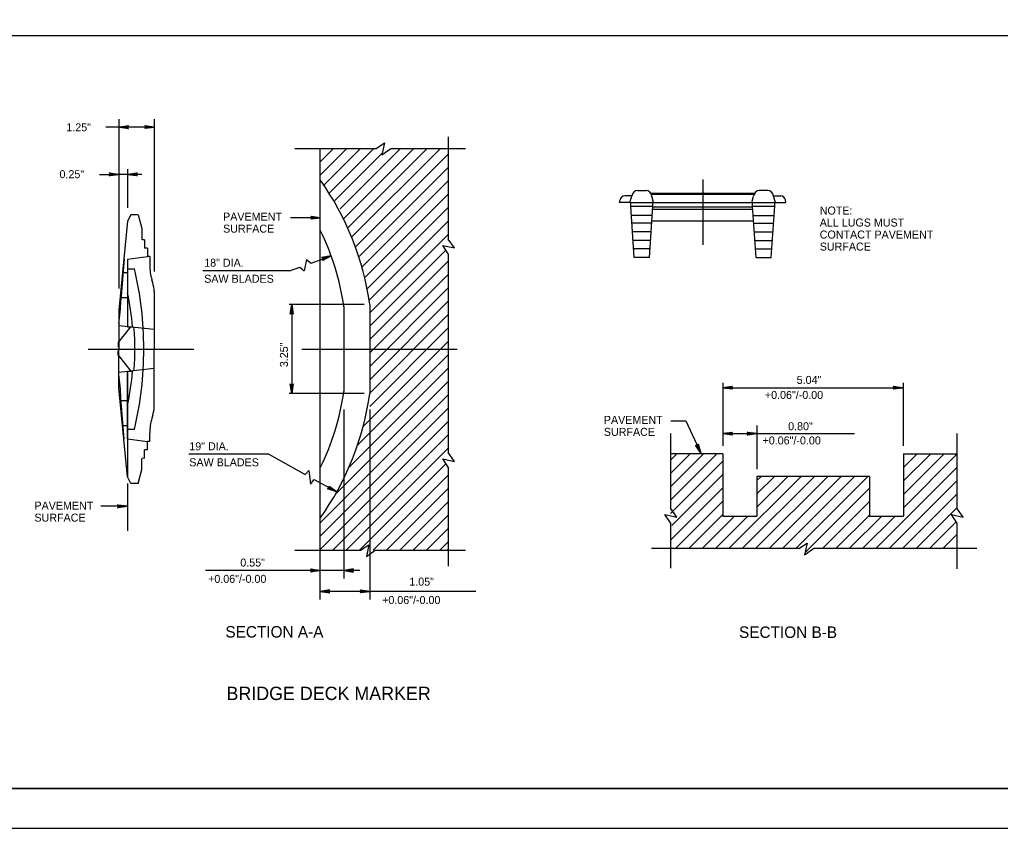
# Model space of a CAD drawing. Extents: x 639362 to 641108, y 298458 to 299646.
# Drawn here: x 640431.7 to 640799.3, y 298457.6 to 298760.6 of the extents above; entities that cross this region are included whole.
import ezdxf

# ---------------------------------------------------------------- set-up
doc = ezdxf.new("R2010")
doc.units = 0
for name, color, linetype in [('1', 7, 'Continuous'), ('2', 7, 'Continuous'), ('PLT-BNDY', 7, 'Continuous')]:
    doc.layers.add(name, color=color, linetype=linetype)

msp = doc.modelspace()

# ---------------------------------------------------------------- linework, layer by layer
at = {"layer": '1'}
for p, q in [((640243.31, 298754.63), (640829.31, 298754.63)), ((641029.31, 298472.63), (640243.31, 298472.63)), ((640243.31, 298472.63), (640829.31, 298472.63))]:
    msp.add_line(p, q, dxfattribs=at)
at = {"layer": '2'}
for p, q in [((640468.92, 298723.36), (640468.92, 298659.92)), ((640482.21, 298723.36), (640482.21, 298666.21)), ((640482.21, 298720.36), (640463.98, 298720.36)), ((640565.36, 298712.39), (640568.44, 298714.44)), ((640568.44, 298714.44), (640567.53, 298710.04)), ((640592.33, 298716.72), (640592.33, 298678.38)), ((640534.93, 298712.39), (640565.36, 298712.39)), ((640544.39, 298712.38), (640544.41, 298712.39)), ((640544.39, 298707.37), (640549.41, 298712.39)), ((640544.39, 298702.36), (640554.42, 298712.39)), ((640544.39, 298543.43), (640544.39, 298712.39)), ((640545.44, 298698.39), (640559.43, 298712.39)), ((640547.68, 298695.63), (640564.44, 298712.39)), ((640549.92, 298692.86), (640567.64, 298710.58)), ((640551.84, 298689.77), (640574.46, 298712.39)), ((640553.08, 298686), (640579.47, 298712.39)), ((640554.68, 298682.59), (640584.48, 298712.39)), ((640556.17, 298679.08), (640589.48, 298712.39)), ((640567.53, 298710.04), (640570.82, 298712.39)), ((640570.82, 298712.39), (640598.86, 298712.39)), ((640557.56, 298675.46), (640592.33, 298710.23)), ((640472.14, 298704.67), (640472.14, 298690.08)), ((640558.84, 298671.73), (640592.33, 298705.22)), ((640461.63, 298702.66), (640468.92, 298702.66)), ((640477.55, 298702.66), (640468.92, 298702.66)), ((640560, 298667.88), (640592.33, 298700.21)), ((640687.74, 298700.77), (640687.74, 298676.31)), ((640663.27, 298696.59), (640666.56, 298696.59)), ((640712.21, 298696.59), (640708.92, 298696.59)), ((640561.03, 298663.91), (640592.33, 298695.2)), ((640656.61, 298692.1), (640656.76, 298693.07)), ((640660.72, 298692.1), (640656.61, 298692.1)), ((640661.18, 298694.57), (640658.51, 298694.57)), ((640660.47, 298692.1), (640661.17, 298694.53)), ((640660.47, 298692.1), (640669.35, 298692.1)), ((640660.76, 298690.78), (640660.76, 298692.1)), ((640668.24, 298695.6), (640707.24, 298695.6)), ((640668.46, 298695.2), (640707.06, 298695.2)), ((640669.35, 298692.1), (640668.66, 298694.53)), ((640669.06, 298690.78), (640669.06, 298692.1)), ((640669.1, 298692.1), (640706.37, 298692.1)), ((640706.13, 298692.1), (640706.82, 298694.53)), ((640706.13, 298692.1), (640715, 298692.1)), ((640706.41, 298690.78), (640706.41, 298692.1)), ((640714.3, 298694.57), (640716.97, 298694.57)), ((640715, 298692.1), (640714.31, 298694.53)), ((640714.72, 298690.78), (640714.72, 298692.1)), ((640714.76, 298692.1), (640718.87, 298692.1)), ((640718.87, 298692.1), (640718.72, 298693.07)), ((640561.93, 298659.79), (640592.33, 298690.19)), ((640662.09, 298671.5), (640660.76, 298690.78)), ((640660.76, 298690.78), (640669.06, 298690.78)), ((640667.74, 298671.5), (640669.06, 298690.78)), ((640668.98, 298689.63), (640706.49, 298689.63)), ((640669.05, 298690.55), (640706.43, 298690.55)), ((640707.74, 298671.5), (640706.41, 298690.78)), ((640706.41, 298690.78), (640714.72, 298690.78)), ((640713.38, 298671.5), (640714.72, 298690.78)), ((640472.14, 298685.17), (640468.92, 298651.74)), ((640473.47, 298687.55), (640472.14, 298685.17)), ((640476.19, 298687.55), (640473.47, 298687.55)), ((640476.19, 298687.55), (640477.59, 298682.33)), ((640544.39, 298686.43), (640533.26, 298686.43)), ((640562.68, 298655.53), (640592.33, 298685.18)), ((640668.82, 298687.21), (640661.01, 298687.21)), ((640668.69, 298685.3), (640706.79, 298685.3)), ((640706.66, 298687.21), (640714.47, 298687.21)), ((640477.59, 298682.33), (640477.59, 298678.19)), ((640668.62, 298684.35), (640661.2, 298684.35)), ((640668.4, 298681.14), (640661.43, 298681.14)), ((640706.85, 298684.35), (640714.27, 298684.35)), ((640707.08, 298681.14), (640714.05, 298681.14)), ((640478.57, 298678.17), (640477.7, 298678.19)), ((640478.57, 298678.17), (640478.57, 298675.06)), ((640562.92, 298650.77), (640592.33, 298680.18)), ((640594.68, 298675.09), (640592.33, 298678.38)), ((640668.18, 298677.93), (640661.65, 298677.93)), ((640707.3, 298677.93), (640713.83, 298677.93)), ((640479.64, 298675.04), (640478.57, 298675.06)), ((640479.64, 298675.04), (640479.64, 298671.93)), ((640562.92, 298645.76), (640591.43, 298674.27)), ((640592.33, 298672.91), (640590.28, 298675.99)), ((640590.28, 298675.99), (640594.68, 298675.09)), ((640667.96, 298674.71), (640661.87, 298674.71)), ((640707.52, 298674.71), (640713.6, 298674.71)), ((640470.85, 298670.98), (640469.68, 298655.59)), ((640472.14, 298670.91), (640479.64, 298671.93)), ((640472.14, 298670.91), (640472.14, 298645.64)), ((640480.51, 298671.91), (640479.64, 298671.93)), ((640480.51, 298671.91), (640480.51, 298668.68)), ((640539.27, 298670.8), (640538.32, 298666.53)), ((640539.27, 298670.8), (640540.95, 298669.38)), ((640540.95, 298669.38), (640548.48, 298672.12)), ((640562.92, 298640.75), (640592.33, 298670.16)), ((640592.33, 298672.91), (640592.33, 298598.42)), ((640667.74, 298671.5), (640662.09, 298671.5)), ((640707.74, 298671.5), (640713.38, 298671.5)), ((640472.14, 298667.32), (640474.77, 298667.32)), ((640532.89, 298666.46), (640500.42, 298666.46)), ((640532.89, 298666.46), (640536.74, 298667.86)), ((640536.74, 298667.86), (640538.32, 298666.53)), ((640470.46, 298665.86), (640472.14, 298665.86)), ((640481.61, 298662.05), (640481.29, 298663.16)), ((640562.92, 298635.74), (640592.33, 298665.15)), ((640562.92, 298630.73), (640592.33, 298660.14)), ((640469.68, 298656.51), (640472.14, 298656.51)), ((640482.14, 298658.81), (640482.14, 298637.23)), ((640468.92, 298651.74), (640468.92, 298637.23)), ((640560.92, 298653.87), (640532.71, 298653.87)), ((640533.71, 298653.87), (640533.71, 298620.58)), ((640553.25, 298653.19), (640553.25, 298621.27)), ((640562.92, 298625.73), (640592.33, 298655.13)), ((640562.92, 298653.87), (640562.92, 298620.58)), ((640562.92, 298620.72), (640592.33, 298650.12)), ((640468.65, 298639.55), (640473.41, 298645.55)), ((640482.14, 298644.53), (640468.92, 298645.97)), ((640472.14, 298645.53), (640473.69, 298645.53)), ((640562.92, 298615.71), (640592.33, 298645.11)), ((640457.4, 298637.23), (640496.99, 298637.23)), ((640468.65, 298639.55), (640468.65, 298637.97)), ((640468.92, 298622.71), (640468.92, 298637.23)), ((640482.14, 298615.64), (640482.14, 298637.23)), ((640537.51, 298637.23), (640595.72, 298637.23)), ((640560.45, 298608.23), (640592.33, 298640.1)), ((640468.65, 298634.9), (640468.65, 298636.49)), ((640468.65, 298634.9), (640473.41, 298628.91)), ((640558.29, 298601.06), (640592.33, 298635.1)), ((640482.14, 298629.92), (640468.92, 298628.48)), ((640555.13, 298592.89), (640592.33, 298630.09)), ((640472.14, 298628.93), (640473.69, 298628.93)), ((640472.14, 298628.81), (640472.14, 298589.29)), ((640472.14, 298603.55), (640472.14, 298628.81)), ((640472.14, 298589.29), (640468.92, 298622.71)), ((640550.12, 298582.87), (640592.33, 298625.08)), ((640695.32, 298624.5), (640695.32, 298601)), ((640695.32, 298622.72), (640762.65, 298622.72)), ((640762.82, 298624.5), (640762.82, 298601)), ((640470.85, 298603.47), (640469.68, 298618.86)), ((640560.92, 298620.58), (640532.71, 298620.58)), ((640544.39, 298572.13), (640592.33, 298620.07)), ((640469.68, 298617.94), (640472.14, 298617.94)), ((640544.39, 298567.13), (640592.33, 298615.06)), ((640481.61, 298612.41), (640481.29, 298611.29)), ((640553.25, 298614.58), (640553.25, 298551.25)), ((640562.92, 298614.58), (640562.92, 298543.43)), ((640470.46, 298608.59), (640472.14, 298608.59)), ((640544.39, 298562.12), (640592.33, 298610.05)), ((640675.82, 298610.34), (640681.38, 298610.34)), ((640681.38, 298610.34), (640687.01, 298598.21)), ((640708.07, 298608.54), (640708.07, 298592.22)), ((640472.14, 298607.14), (640474.77, 298607.14)), ((640480.51, 298602.55), (640480.51, 298605.78)), ((640549.15, 298561.86), (640592.33, 298605.04)), ((640675.65, 298605.61), (640675.65, 298577.57)), ((640695.32, 298605.54), (640744.68, 298605.54)), ((640783.03, 298605.61), (640783.03, 298577.57)), ((640472.14, 298603.55), (640479.64, 298602.53)), ((640480.51, 298602.55), (640479.64, 298602.53)), ((640479.64, 298599.42), (640479.64, 298602.53)), ((640479.64, 298599.42), (640478.57, 298599.4)), ((640478.57, 298596.29), (640478.57, 298599.4)), ((640525.09, 298597.85), (640495.09, 298597.85)), ((640525.09, 298597.85), (640538.78, 298590.23)), ((640554.15, 298561.86), (640592.33, 298600.04)), ((640594.68, 298595.13), (640592.33, 298598.42)), ((640695.32, 298598), (640675.65, 298598)), ((640675.65, 298595.64), (640678.02, 298598)), ((640675.65, 298590.63), (640683.03, 298598)), ((640675.65, 298585.62), (640688.04, 298598)), ((640675.65, 298580.61), (640693.04, 298598)), ((640695.32, 298598), (640695.32, 298574.53)), ((640762.96, 298598), (640762.96, 298574.63)), ((640762.96, 298598), (640783.03, 298598)), ((640762.96, 298582.78), (640778.19, 298598)), ((640762.96, 298587.78), (640773.18, 298598)), ((640762.96, 298592.79), (640768.17, 298598)), ((640762.96, 298577.77), (640783.03, 298597.84)), ((640477.59, 298592.12), (640477.59, 298596.27)), ((640478.57, 298596.29), (640477.7, 298596.27)), ((640559.16, 298561.86), (640591.5, 298594.2)), ((640592.33, 298592.95), (640590.28, 298596.03)), ((640590.28, 298596.03), (640594.68, 298595.13)), ((640592.33, 298592.95), (640592.33, 298555.85)), ((640675.65, 298575.6), (640695.32, 298595.27)), ((640752.65, 298562.45), (640783.03, 298592.83)), ((640473.47, 298586.9), (640472.14, 298589.29)), ((640476.19, 298586.9), (640477.59, 298592.12)), ((640538.78, 298590.23), (640540.06, 298591.76)), ((640540.06, 298591.76), (640540.71, 298586.58)), ((640564.17, 298561.86), (640592.33, 298590.02)), ((640676.16, 298571.1), (640695.32, 298590.27)), ((640697.56, 298562.45), (640724.61, 298589.5)), ((640702.57, 298562.45), (640729.62, 298589.5)), ((640707.58, 298562.45), (640734.63, 298589.5)), ((640708.07, 298589.5), (640708.07, 298574.63)), ((640750.21, 298589.5), (640708.07, 298589.5)), ((640708.07, 298587.99), (640709.59, 298589.5)), ((640708.07, 298582.98), (640714.6, 298589.5)), ((640708.07, 298577.97), (640719.6, 298589.5)), ((640712.59, 298562.45), (640739.64, 298589.5)), ((640717.59, 298562.45), (640744.65, 298589.5)), ((640722.6, 298562.45), (640749.66, 298589.5)), ((640750.21, 298589.5), (640750.21, 298574.53)), ((640472.14, 298586.8), (640472.14, 298569.08)), ((640476.19, 298586.9), (640473.47, 298586.9)), ((640540.71, 298586.58), (640542.17, 298588.34)), ((640542.17, 298588.34), (640550.57, 298583.67)), ((640757.66, 298562.45), (640783.03, 298587.82)), ((640569.18, 298561.86), (640592.33, 298585.01)), ((640675.65, 298565.59), (640695.32, 298585.26)), ((640726.11, 298560.95), (640750.21, 298585.05)), ((640762.67, 298562.45), (640783.03, 298582.81)), ((640472.04, 298578.32), (640462.16, 298578.32)), ((640574.19, 298561.86), (640592.33, 298580)), ((640677.53, 298562.45), (640695.32, 298580.25)), ((640732.62, 298562.45), (640750.21, 298580.04)), ((640579.2, 298561.86), (640592.33, 298574.99)), ((640675.65, 298572.11), (640673.6, 298575.19)), ((640673.6, 298575.19), (640678, 298574.28)), ((640678, 298574.28), (640675.65, 298577.57)), ((640682.53, 298562.45), (640695.32, 298575.24)), ((640687.54, 298562.45), (640699.66, 298574.57)), ((640692.55, 298562.45), (640704.7, 298574.6)), ((640695.32, 298574.63), (640708.07, 298574.63)), ((640737.63, 298562.45), (640750.21, 298575.03)), ((640742.64, 298562.45), (640754.82, 298574.63)), ((640747.64, 298562.45), (640759.82, 298574.63)), ((640750.21, 298574.63), (640762.96, 298574.63)), ((640767.68, 298562.45), (640782.93, 298577.71)), ((640783.03, 298572.11), (640780.98, 298575.19)), ((640780.98, 298575.19), (640785.38, 298574.28)), ((640785.38, 298574.28), (640783.03, 298577.57)), ((640675.65, 298572.11), (640675.65, 298555.07)), ((640772.69, 298562.45), (640782.75, 298572.52)), ((640783.03, 298572.11), (640783.03, 298554.84)), ((640584.21, 298561.86), (640592.33, 298569.98)), ((640777.7, 298562.45), (640783.03, 298567.78)), ((640559.51, 298561.86), (640562.59, 298563.91)), ((640562.59, 298563.91), (640561.68, 298559.51)), ((640589.21, 298561.86), (640592.33, 298564.98)), ((640723.76, 298562.45), (640726.84, 298564.5)), ((640726.84, 298564.5), (640725.93, 298560.1)), ((640534.93, 298561.86), (640559.51, 298561.86)), ((640561.68, 298559.51), (640564.97, 298561.86)), ((640564.97, 298561.86), (640598.86, 298561.86)), ((640591.97, 298561.86), (640592.33, 298562.18)), ((640723.76, 298562.45), (640668.55, 298562.45)), ((640725.93, 298560.1), (640729.22, 298562.45)), ((640790.48, 298562.45), (640729.22, 298562.45)), ((640553.25, 298554.25), (640501.33, 298554.25)), ((640559.21, 298554.25), (640553.25, 298554.25)), ((640562.92, 298546.43), (640544.39, 298546.43)), ((640602.7, 298546.43), (640562.92, 298546.43))]:
    msp.add_line(p, q, dxfattribs=at)
for points in [[(640472.32, 298719.93), (640472.2, 298720.18), (640468.92, 298720.36), (640472.32, 298719.93), (640472.5, 298719.78), (640468.92, 298720.36), (640472.19, 298720.52), (640472.31, 298720.76), (640468.92, 298720.36), (640472.5, 298720.93), (640472.31, 298720.76)], [(640478.8, 298720.79), (640478.93, 298720.54), (640482.21, 298720.36), (640478.8, 298720.79), (640478.63, 298720.93), (640482.21, 298720.36), (640478.93, 298720.19), (640478.81, 298719.95), (640482.21, 298720.36), (640478.63, 298719.79), (640478.81, 298719.95)], [(640465.51, 298703.09), (640465.64, 298702.85), (640468.92, 298702.66), (640465.51, 298703.09), (640465.34, 298703.24), (640468.92, 298702.66), (640465.64, 298702.5), (640465.52, 298702.26), (640468.92, 298702.66), (640465.34, 298702.1), (640465.52, 298702.26)], [(640475.55, 298702.23), (640475.42, 298702.48), (640472.14, 298702.66), (640475.55, 298702.23), (640475.73, 298702.08), (640472.14, 298702.66), (640475.42, 298702.82), (640475.54, 298703.07), (640472.14, 298702.66), (640475.73, 298703.23), (640475.54, 298703.07)], [(640540.99, 298686.86), (640541.11, 298686.61), (640544.39, 298686.43), (640540.99, 298686.86), (640540.81, 298687.01), (640544.39, 298686.43), (640541.12, 298686.26), (640541, 298686.02), (640544.39, 298686.43), (640540.81, 298685.86), (640541, 298686.02)], [(640545.41, 298670.58), (640545.45, 298670.85), (640548.48, 298672.12), (640545.41, 298670.58), (640545.3, 298670.38), (640548.48, 298672.12), (640545.34, 298671.18), (640545.14, 298671.37), (640548.48, 298672.12), (640544.92, 298671.46), (640545.14, 298671.37)], [(640533.28, 298650.46), (640533.53, 298650.59), (640533.71, 298653.87), (640533.28, 298650.46), (640533.13, 298650.29), (640533.71, 298653.87), (640533.87, 298650.6), (640534.11, 298650.48), (640533.71, 298653.87), (640534.28, 298650.29), (640534.11, 298650.48)], [(640534.14, 298623.99), (640533.89, 298623.86), (640533.71, 298620.58), (640534.14, 298623.99), (640534.29, 298624.16), (640533.71, 298620.58), (640533.54, 298623.86), (640533.3, 298623.98), (640533.71, 298620.58), (640533.14, 298624.16), (640533.3, 298623.98)], [(640698.73, 298622.3), (640698.6, 298622.54), (640695.32, 298622.72), (640698.73, 298622.3), (640698.9, 298622.15), (640695.32, 298622.72), (640698.6, 298622.89), (640698.72, 298623.13), (640695.32, 298622.72), (640698.9, 298623.29), (640698.72, 298623.13)], [(640759.25, 298623.15), (640759.38, 298622.9), (640762.65, 298622.72), (640759.25, 298623.15), (640759.08, 298623.3), (640762.65, 298622.72), (640759.38, 298622.56), (640759.26, 298622.32), (640762.65, 298622.72), (640759.08, 298622.15), (640759.26, 298622.32)], [(640698.73, 298605.11), (640698.6, 298605.36), (640695.32, 298605.54), (640698.73, 298605.11), (640698.9, 298604.96), (640695.32, 298605.54), (640698.6, 298605.7), (640698.72, 298605.94), (640695.32, 298605.54), (640698.9, 298606.11), (640698.72, 298605.94)], [(640704.59, 298605.96), (640704.72, 298605.72), (640708, 298605.53), (640704.59, 298605.96), (640704.42, 298606.11), (640708, 298605.53), (640704.73, 298605.37), (640704.6, 298605.13), (640708, 298605.53), (640704.42, 298604.97), (640704.6, 298605.13)], [(640685.96, 298601.48), (640685.79, 298601.26), (640687.01, 298598.21), (640685.96, 298601.48), (640686.03, 298601.7), (640687.01, 298598.21), (640685.48, 298601.12), (640685.21, 298601.12), (640687.01, 298598.21), (640684.99, 298601.22), (640685.21, 298601.12)], [(640547.77, 298585.66), (640547.77, 298585.39), (640550.57, 298583.67), (640547.77, 298585.66), (640547.69, 298585.87), (640550.57, 298583.67), (640547.6, 298585.08), (640547.38, 298584.92), (640550.57, 298583.67), (640547.15, 298584.87), (640547.38, 298584.92)], [(640468.63, 298578.75), (640468.76, 298578.5), (640472.04, 298578.32), (640468.63, 298578.75), (640468.46, 298578.9), (640472.04, 298578.32), (640468.76, 298578.16), (640468.64, 298577.91), (640472.04, 298578.32), (640468.46, 298577.75), (640468.64, 298577.91)], [(640540.99, 298554.68), (640541.12, 298554.43), (640544.39, 298554.25), (640540.99, 298554.68), (640540.81, 298554.83), (640544.39, 298554.25), (640541.12, 298554.09), (640541, 298553.85), (640544.39, 298554.25), (640540.81, 298553.68), (640541, 298553.85)], [(640556.65, 298554.68), (640556.52, 298554.43), (640553.25, 298554.25), (640556.65, 298554.68), (640556.83, 298554.83), (640553.25, 298554.25), (640556.52, 298554.09), (640556.64, 298553.85), (640553.25, 298554.25), (640556.83, 298553.68), (640556.64, 298553.85)], [(640547.8, 298546.86), (640547.67, 298546.61), (640544.39, 298546.43), (640547.8, 298546.86), (640547.97, 298547.01), (640544.39, 298546.43), (640547.67, 298546.27), (640547.79, 298546.03), (640544.39, 298546.43), (640547.97, 298545.86), (640547.79, 298546.03)], [(640559.52, 298546.86), (640559.65, 298546.61), (640562.92, 298546.43), (640559.52, 298546.86), (640559.34, 298547.01), (640562.92, 298546.43), (640559.65, 298546.27), (640559.53, 298546.03), (640562.92, 298546.43), (640559.34, 298545.86), (640559.53, 298546.03)]]:
    msp.add_lwpolyline(points, dxfattribs=at)
for centre, radius, start, end in [((640458.11, 298639.32), 105.82, 7.9054, 35.3742), ((640658.51, 298692.8), 1.77, 90, 171.2194), ((640716.97, 298692.8), 1.77, 8.7806, 90), ((640458.11, 298639.32), 96.14, 8.2945, 26.1755), ((640500.51, 298668.68), 20, 180, 196.0037), ((640472.14, 298658.81), 10, 0, 18.8675), ((640372.27, 298636.71), 102.18, 4.9359, 12.1966), ((640372.27, 298636.71), 102.68, 0.2899, 4.891), ((640372.27, 298637.75), 102.68, 355.109, 359.7101), ((640372.27, 298637.75), 102.18, 347.8034, 355.0641), ((640458.11, 298635.14), 96.14, 333.8245, 351.7055), ((640458.11, 298635.14), 105.82, 324.6258, 352.0946), ((640472.14, 298615.64), 10, 341.1325, 0), ((640500.51, 298605.78), 20, 163.9963, 180)]:
    msp.add_arc(centre, radius, start, end, dxfattribs=at)
for centre, major_axis, ratio, start_param, end_param in [((640663.27, 298693.94), (0, 2.66), 0.81, 0, 1.34621), ((640666.56, 298693.94), (0, 2.66), 0.81, 4.937133, 6.283185), ((640708.92, 298693.94), (0, 2.66), 0.81, 0, 1.346052), ((640712.21, 298693.94), (0, 2.66), 0.81, 4.936975, 6.283185), ((640392.23, 298637.23), (0, -106.68), 0.806534, 1.570813, 1.856752), ((640458.96, 298657.48), (0, -28.55), 0.376297, 1.186589, 1.504441), ((640392.23, 298637.23), (0, 106.68), 0.806534, 4.426434, 4.712372), ((640458.96, 298616.97), (0, 28.55), 0.376297, 4.778744, 5.096596)]:
    msp.add_ellipse(centre, major_axis=major_axis, ratio=ratio, start_param=start_param, end_param=end_param, dxfattribs=at)
at = {"layer": 'PLT-BNDY'}
msp.add_lwpolyline([(640203.31, 299051.63), (641044.31, 299051.63), (641044.31, 298457.63), (640203.31, 298457.63)], close=True, dxfattribs=at)

# ---------------------------------------------------------------- texts
at = {"layer": '2'}
for s, height, p in [('1.25"', 3, (640449.23, 298718.79)), ('0.25"', 3, (640446.68, 298701.23)), ('NOTE:', 3, (640731.6, 298687.61)), ('PAVEMENT', 3, (640507.98, 298685.33)), ('ALL LUGS MUST ', 3.0001, (640731.6, 298683.11)), ('SURFACE', 3, (640507.98, 298680.83)), ('CONTACT PAVEMENT', 3.0001, (640731.6, 298678.61)), ('SURFACE', 3, (640731.6, 298674.11)), ('18" DIA.', 3, (640500.91, 298668.05)), ('SAW BLADES', 3, (640500.91, 298662.05)), ('5.04"', 3, (640722.96, 298624.15)), ('+0.06"/-0.00', 3, (640711.04, 298618.52)), ('PAVEMENT', 3, (640650.69, 298609.19)), ('SURFACE', 3, (640650.69, 298604.69)), ('0.80"', 3, (640719.76, 298606.8)), ('+0.06"/-0.00', 3, (640710.16, 298601.48)), ('19" DIA.', 3, (640495.32, 298599.28)), ('SAW BLADES', 3, (640495.32, 298593.28)), ('PAVEMENT', 3, (640437.28, 298577.05)), ('SURFACE', 3, (640437.28, 298572.55)), ('0.55"', 3, (640514.44, 298555.72)), ('+0.06"/-0.00', 3, (640502.37, 298549.62)), ('1.05"', 3, (640577.78, 298548.56)), ('+0.06"/-0.00', 3, (640567.59, 298541.69)), ('SECTION A-A', 4.3, (640508.85, 298529.12)), ('SECTION B-B', 4.3, (640701.35, 298528.98)), ('BRIDGE DECK MARKER', 5, (640509.27, 298505.71))]:
    msp.add_text(s, height=height, dxfattribs=at).set_placement(p)
msp.add_text('3.25"', height=3, rotation=90, dxfattribs=at).set_placement((640532.29, 298630.43))

doc.saveas('drawing.dxf')
